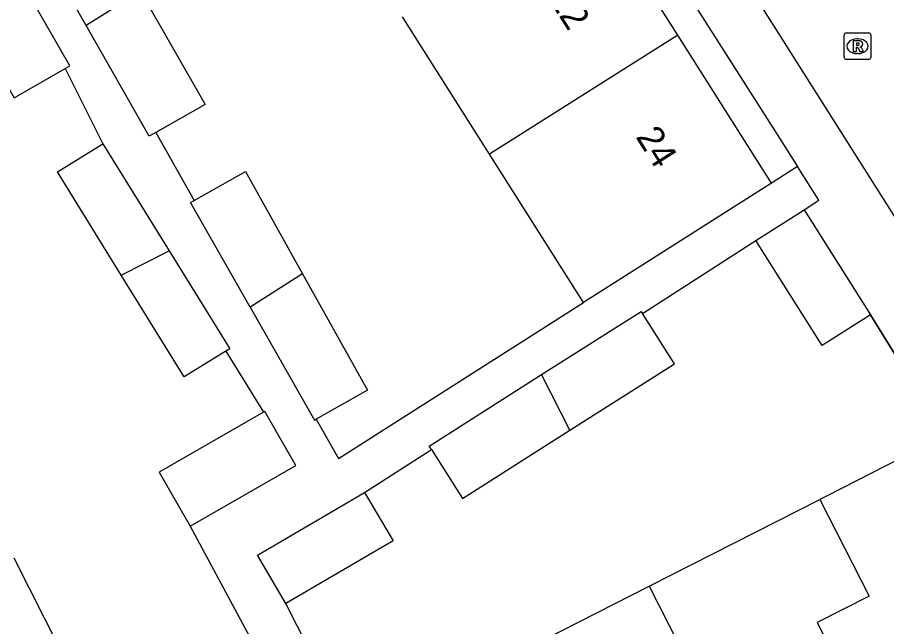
# Model space of a CAD drawing. Extents: x 162347 to 162868, y 381221 to 381813.
# Drawn here: x 162493.3 to 162526.14, y 381550.31 to 381573.33 of the extents above; entities that cross this region are included whole.
import ezdxf

# ---------------------------------------------------------------- set-up
doc = ezdxf.new("R2010")
doc.units = 0
for name, color, linetype in [('IMGEO_Muur', 7, 'Continuous'), ('IMGEO_Pand', 7, 'Continuous'), ('IMGEO_Pand_nummerreeks', 7, 'Continuous'), ('IMGEO_Rijbaan_lokaal_open', 7, 'Continuous'), ('IMGEO_Rioolput', 7, 'Continuous'), ('IMGEO_Voetpad_open', 7, 'Continuous')]:
    doc.layers.add(name, color=color, linetype=linetype)

msp = doc.modelspace()

# ---------------------------------------------------------------- linework, layer by layer
at = {"layer": 'IMGEO_Muur'}
msp.add_lwpolyline([(162528.355, 381557.526), (162525.538, 381562.087)], dxfattribs=at)
at = {"layer": 'IMGEO_Pand'}
for points in [[(162518.25, 381572.651), (162514.958, 381577.839)], [(162495.897, 381573.025), (162493.64, 381576.985), (162493.898, 381577.132)], [(162495.112, 381571.395), (162495.286, 381571.494), (162492.949, 381575.568)], [(162490.799, 381574.472), (162493.18, 381570.294), (162495.112, 381571.395)], [(162497.95, 381574.323), (162495.897, 381573.025)], [(162497.95, 381574.323), (162500.393, 381570.038), (162498.528, 381568.975)], [(162511.145, 381568.155), (162507.854, 381573.343)], [(162498.528, 381568.975), (162498.285, 381568.836), (162495.897, 381573.025)], [(162518.25, 381572.651), (162511.145, 381568.155)], [(162521.79, 381567.07), (162518.25, 381572.651)], [(162497.224, 381563.592), (162494.814, 381567.487), (162496.533, 381568.551)], [(162496.533, 381568.551), (162499.033, 381564.511)], [(162514.696, 381562.558), (162511.145, 381568.155)], [(162499.984, 381566.41), (162501.917, 381567.51), (162504.072, 381563.644)], [(162521.79, 381567.07), (162514.696, 381562.558)], [(162502.096, 381562.38), (162499.846, 381566.331), (162499.984, 381566.41)], [(162521.196, 381564.895), (162523.028, 381566.054)], [(162523.028, 381566.054), (162525.538, 381562.087)], [(162525.538, 381562.087), (162523.706, 381560.928), (162521.196, 381564.895)], [(162497.224, 381563.592), (162499.033, 381564.511)], [(162499.033, 381564.511), (162501.325, 381560.806), (162501.174, 381560.712)], [(162501.174, 381560.712), (162499.606, 381559.742), (162497.224, 381563.592)], [(162504.072, 381563.644), (162502.096, 381562.38)], [(162504.072, 381563.644), (162506.525, 381559.243), (162504.594, 381558.143)], [(162502.096, 381562.38), (162504.529, 381558.106), (162504.594, 381558.143)], [(162513.107, 381559.832), (162516.87, 381562.222), (162516.921, 381562.142)], [(162514.176, 381557.73), (162518.128, 381560.24), (162516.921, 381562.142)], [(162508.942, 381557.004), (162508.859, 381557.134), (162513.107, 381559.832)], [(162514.176, 381557.73), (162513.107, 381559.832)], [(162499.827, 381554.108), (162503.819, 381556.4), (162502.65, 381558.436), (162502.602, 381558.408)], [(162502.602, 381558.408), (162498.658, 381556.144), (162499.827, 381554.108)], [(162508.942, 381557.004), (162510.117, 381555.152), (162514.176, 381557.73)], [(162528.355, 381557.526), (162523.899, 381555.258), (162523.625, 381555.117)], [(162503.446, 381551.184), (162502.375, 381553.012), (162506.422, 381555.381)], [(162506.422, 381555.381), (162507.493, 381553.553), (162503.446, 381551.184)], [(162517.175, 381551.836), (162523.625, 381555.117)], [(162523.625, 381555.117), (162525.484, 381551.465), (162523.52, 381550.466), (162525.378, 381546.813)], [(162493.17, 381552.905), (162495.445, 381548.407)], [(162510.497, 381548.437), (162517.175, 381551.836)], [(162517.175, 381551.836), (162520.892, 381544.53)]]:
    msp.add_lwpolyline(points, dxfattribs=at)
at = {"layer": 'IMGEO_Rijbaan_lokaal_open'}
msp.add_lwpolyline([(162536.173, 381550.404), (162533.548, 381554.605), (162528.482, 381562.594), (162519.683, 381576.506), (162509.771, 381592.107), (162504.221, 381600.859)], dxfattribs=at)
at = {"layer": 'IMGEO_Rioolput'}
for p, q in [((162524.545, 381571.812), (162524.545, 381572.664)), ((162524.62, 381572.738), (162525.472, 381572.738)), ((162525.546, 381572.664), (162525.546, 381571.812)), ((162525.033, 381572.518), (162525.058, 381572.518)), ((162525.056, 381571.958), (162525.031, 381571.958)), ((162525.472, 381571.738), (162524.62, 381571.738))]:
    msp.add_line(p, q, dxfattribs=at)
for points in [[(162524.545, 381571.812), (162524.545, 381572.664)], [(162524.62, 381572.738), (162525.472, 381572.738)], [(162525.546, 381572.664), (162525.546, 381571.812)], [(162525.134, 381572.436), (162524.882, 381572.438), (162524.882, 381572.038)], [(162525.06, 381572.357), (162525.006, 381572.357), (162525.006, 381572.276)], [(162525.006, 381572.276), (162525.058, 381572.276)], [(162524.882, 381572.038), (162525.006, 381572.038), (162525.006, 381572.2), (162525.017, 381572.2)], [(162525.064, 381572.171), (162525.135, 381572.038), (162525.275, 381572.038), (162525.21, 381572.164)], [(162525.472, 381571.738), (162524.62, 381571.738)]]:
    msp.add_lwpolyline(points, dxfattribs=at)
for centre, radius, start, end in [((162524.622, 381572.662), 0.0765, 91.552, 178.448), ((162524.622, 381572.662), 0.0765, 91.552, 178.448), ((162525.47, 381572.662), 0.0765, 1.552, 88.448), ((162525.47, 381572.662), 0.0765, 1.552, 88.448), ((162525.042, 381572.465), 0.19, 274.7715, 282.9687), ((162525.066, 381572.261), 0.0964, 77.0061, 93.1865), ((162525.08, 381572.318), 0.0378, 276.6634, 79.6772), ((162525.133, 381572.326), 0.109, 350.3612, 89.416), ((162525.131, 381572.326), 0.112, 277.5842, 350.9817), ((162525.115, 381572.111), 0.108, 29.5134, 73.7905), ((162525.016, 381572.147), 0.0533, 26.0293, 88.6989), ((162524.622, 381571.814), 0.0765, 181.552, 268.448), ((162524.622, 381571.814), 0.0765, 181.552, 268.448), ((162525.47, 381571.814), 0.0765, 271.552, 358.448), ((162525.47, 381571.814), 0.0765, 271.552, 358.448)]:
    msp.add_arc(centre, radius, start, end, dxfattribs=at)
for centre, major_axis, ratio, start_param, end_param in [((162525.032, 381572.238), (-0.387, 0.002), 0.722429, 4.712389, 7.853982), ((162525.057, 381572.238), (-0.39, 0.002), 0.717154, 1.570796, 4.712389)]:
    msp.add_ellipse(centre, major_axis=major_axis, ratio=ratio, start_param=start_param, end_param=end_param, dxfattribs=at)
at = {"layer": 'IMGEO_Voetpad_open'}
for points in [[(162482.857, 381630.326), (162500, 381603.428), (162522.094, 381568.761), (162522.773, 381567.696)], [(162495.112, 381571.395), (162496.533, 381568.551)], [(162498.528, 381568.975), (162499.984, 381566.41)], [(162522.773, 381567.696), (162521.79, 381567.07)], [(162523.028, 381566.054), (162523.584, 381566.423), (162522.773, 381567.696)], [(162516.921, 381562.142), (162521.196, 381564.895)], [(162504.594, 381558.143), (162505.429, 381556.664), (162514.696, 381562.558)], [(162525.538, 381562.087), (162528.355, 381557.526)], [(162501.174, 381560.712), (162502.497, 381558.578), (162502.602, 381558.408)], [(162506.422, 381555.381), (162508.942, 381557.004)], [(162499.827, 381554.108), (162502.162, 381549.778)], [(162506.006, 381546.152), (162503.446, 381551.184)]]:
    msp.add_lwpolyline(points, dxfattribs=at)

# ---------------------------------------------------------------- texts
at = {"layer": 'IMGEO_Pand_nummerreeks'}
for s, p in [('22', (162513.344, 381574.028)), ('24', (162516.645, 381568.813))]:
    msp.add_text(s, height=1, rotation=302.3318, dxfattribs=at).set_placement(p)

doc.saveas('drawing.dxf')
